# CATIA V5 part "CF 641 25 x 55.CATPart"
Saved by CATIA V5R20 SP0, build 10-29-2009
Part number: CF 641 25 x 55
Definition: NONE
Nomenclature: CF 641 25 x 55
Source: Unknown
Description: CF 641 25 x 55
Bounding box of the stored display mesh (mm): x -32 to 23, y -22 to 22, z -22 to 22
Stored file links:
  C:\Users\Utente\Desktop\IO LAVORO\3D X SITO CF\X SITO\CF 641\CF 641 25 x 55.CATPart
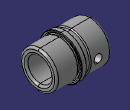
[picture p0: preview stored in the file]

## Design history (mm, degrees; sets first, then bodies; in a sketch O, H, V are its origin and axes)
Body1 "CF 641 25 x 55" (main body)
  Solid1: solid without history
